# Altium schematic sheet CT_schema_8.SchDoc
size 287 x 160 mm
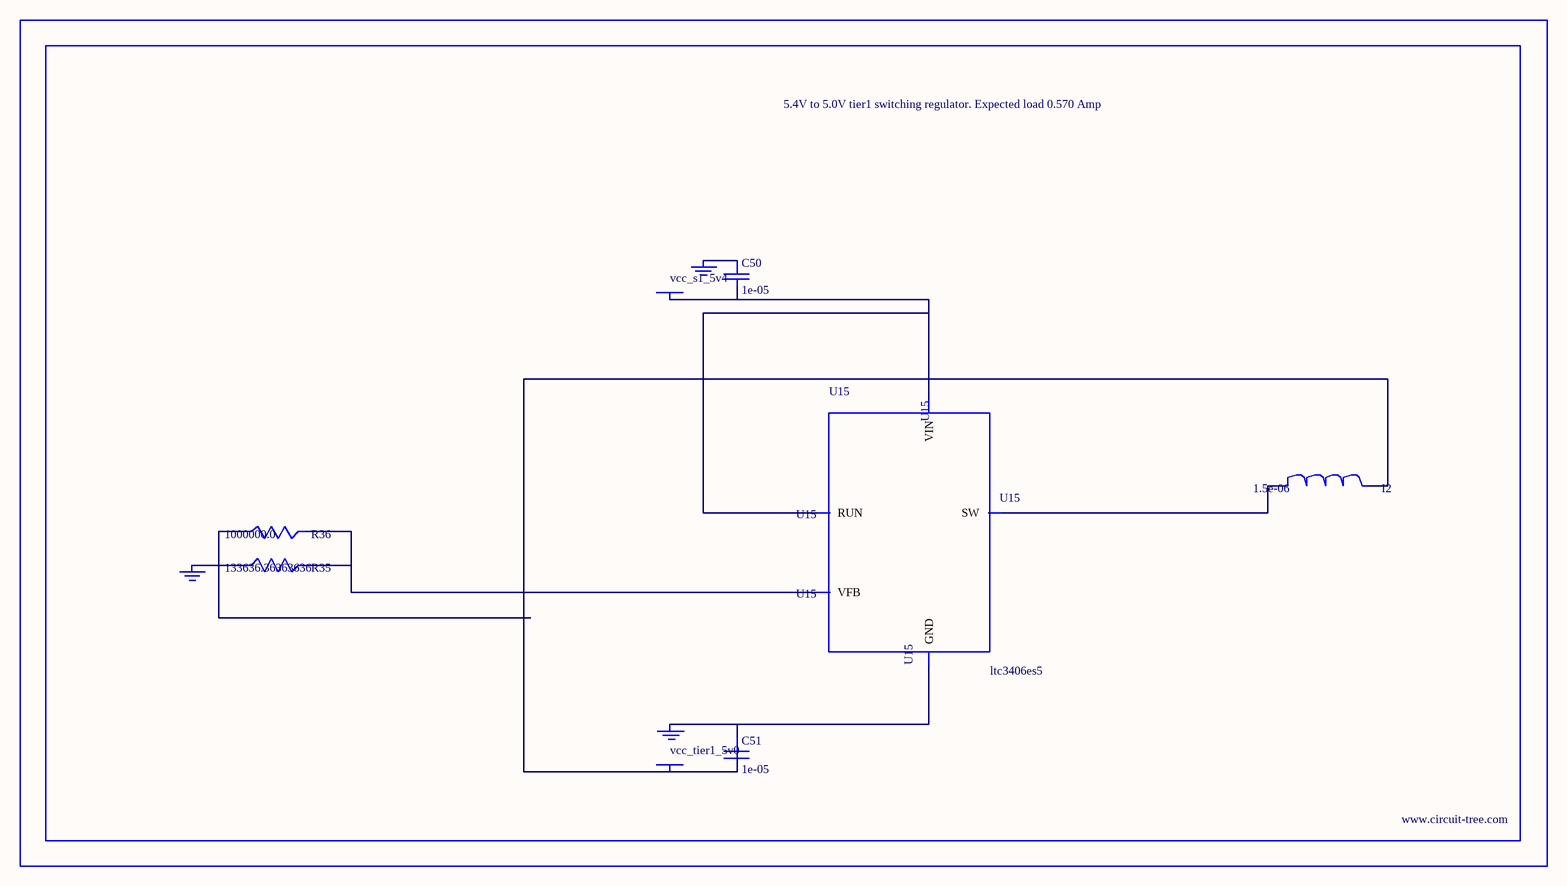
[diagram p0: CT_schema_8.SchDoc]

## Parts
BORDER7  (no value)
C50  1e-05  [C0805]
C51  1e-05  [C0805]
GND_INSTANCE_7_0  (no value)
GND_INSTANCE_7_1  (no value)
GND_INSTANCE_7_2  (no value)
I2  1.5e-06  [L0806]
POWER_INSTANCE_7_0  vcc_tier1_5v0
POWER_INSTANCE_7_1  vcc_s1_5v4
R35  133636.36363636  [R0603]
R36  1000000.0  [R0603]
U15  ltc3406es5  [TSOT-23-5]

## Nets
NetC50_1: C50.1 GND_INSTANCE_7_1.0(GND)
NetC50_2: C50.2 POWER_INSTANCE_7_1.0(PWR) U15.1(RUN) U15.4(VIN)
NetC51_1: C51.1 GND_INSTANCE_7_0.0(GND) U15.2(GND)
NetC51_2: C51.2 I2.2 POWER_INSTANCE_7_0.0(PWR) R36.1
NetGND_INSTANCE_7_2_0: GND_INSTANCE_7_2.0(GND) R35.1
NetI2_1: I2.1 U15.3(SW)
NetR35_2: R35.2 R36.2 U15.5(VFB)

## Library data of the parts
BORDER7 = BORDER_PAGE7
C50 C51 = C0805C106K8RACTU
GND_INSTANCE_7_0-GND_INSTANCE_7_2 = GND
I2 = L0806C1R5MDWIT
POWER_INSTANCE_7_0 POWER_INSTANCE_7_1 = PWR
R35 = R35
R36 = RC0603JR-071ML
